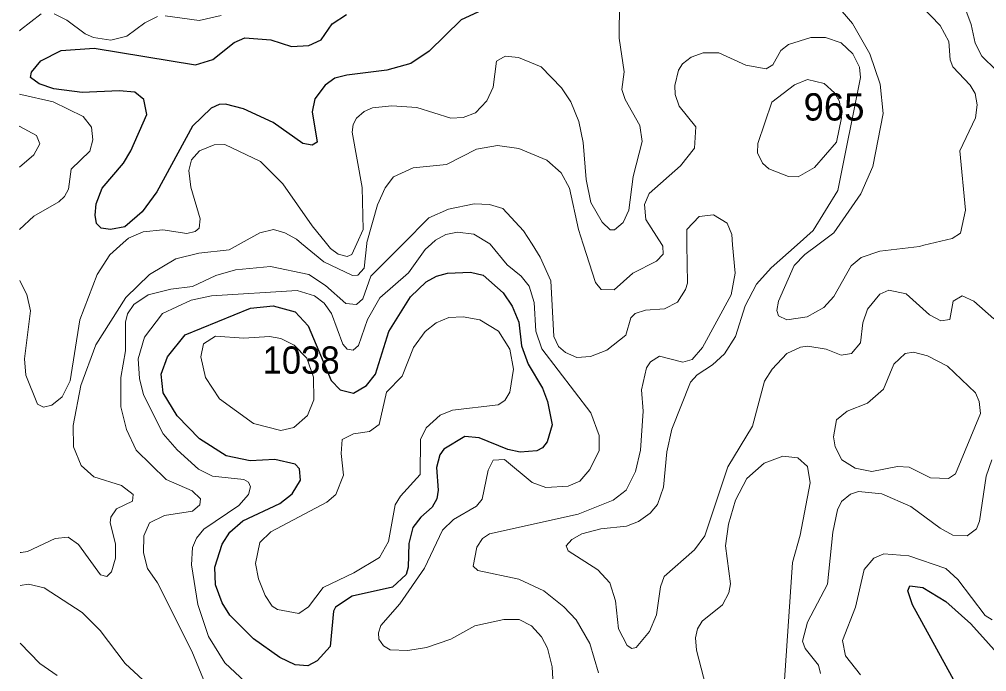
# Model space of a CAD drawing. Extents: x 473.9 to 500, y 7733.1 to 7760.8.
# Drawn here: x 473.9 to 476.736, y 7751.432 to 7753.344 of the extents above; entities that cross this region are included whole.
import ezdxf

# ---------------------------------------------------------------- set-up
doc = ezdxf.new("R2010")
doc.units = 0
doc.header["$LTSCALE"] = 0.032
doc.layers.add('1', color=7, linetype='Continuous', lineweight=25)
doc.layers.add('2', color=7, linetype='Continuous', lineweight=13)
doc.layers.add('21', color=7, linetype='Continuous')

msp = doc.modelspace()

# ---------------------------------------------------------------- linework, layer by layer
at = {"layer": '1'}
for points in [[(475.2698, 7753.3763), (475.1956, 7753.342), (475.1018, 7753.2501), (475.0478, 7753.2148), (474.9783, 7753.1952), (474.861, 7753.1806), (474.8255, 7753.171), (474.7973, 7753.1507), (474.767, 7753.1104), (474.7592, 7753.0728), (474.7738, 7752.9835), (474.7594, 7752.9748), (474.7316, 7752.98), (474.6449, 7753.0418), (474.5579, 7753.0818), (474.5049, 7753.095), (474.486, 7753.0939), (474.4628, 7753.0837), (474.4081, 7753.0306), (474.3035, 7752.8378), (474.2601, 7752.7799), (474.2093, 7752.7353), (474.1675, 7752.7282), (474.1406, 7752.7314), (474.1266, 7752.7453), (474.1224, 7752.7701), (474.1259, 7752.8035), (474.1436, 7752.8493), (474.2055, 7752.9226), (474.2271, 7752.958), (474.2746, 7753.0647), (474.2655, 7753.1084), (474.239, 7753.1302), (474.1933, 7753.1341), (474.085, 7753.1296), (474.0013, 7753.1404), (473.9587, 7753.1549)], [(473.9587, 7753.1549), (473.9328, 7753.1734), (473.9356, 7753.1888), (473.9632, 7753.2219), (474.0228, 7753.2522), (474.1199, 7753.2597), (474.4173, 7753.2102), (474.4673, 7753.226), (474.5301, 7753.2762), (474.5616, 7753.2892), (474.6377, 7753.2838), (474.6979, 7753.2638), (474.7494, 7753.2667), (474.7857, 7753.2839), (474.8175, 7753.331), (474.8592, 7753.3576)], [(476.7469, 7750.9887), (476.7341, 7750.9926), (476.7059, 7751.0101), (476.6612, 7751.0691), (476.624, 7751.1035), (476.6406, 7751.136), (476.6813, 7751.1644), (476.7054, 7751.1938), (476.7121, 7751.2206), (476.7103, 7751.2505), (476.6456, 7751.3979), (476.5186, 7751.6279), (476.5057, 7751.6682), (476.5109, 7751.6832), (476.5489, 7751.678), (476.6169, 7751.6368), (476.6899, 7751.5718), (476.7937, 7751.456)]]:
    msp.add_lwpolyline(points, dxfattribs=at)
msp.add_lwpolyline([(474.6496, 7752.0537), (474.5769, 7752.0498), (474.507, 7752.0644), (474.4285, 7752.1144), (474.3627, 7752.1811), (474.3221, 7752.2486), (474.3163, 7752.3035), (474.3345, 7752.3549), (474.3863, 7752.4186), (474.5782, 7752.4975), (474.6445, 7752.504), (474.7095, 7752.4862), (474.747, 7752.4452), (474.8147, 7752.2849), (474.8415, 7752.2575), (474.8805, 7752.2484), (474.9181, 7752.2705), (474.9444, 7752.3032), (474.9839, 7752.4289), (475.0476, 7752.5308), (475.0934, 7752.5742), (475.1234, 7752.5907), (475.1562, 7752.5998), (475.223, 7752.6028), (475.2603, 7752.594), (475.3187, 7752.5417), (475.3452, 7752.5031), (475.3648, 7752.4561), (475.3724, 7752.387), (475.3925, 7752.3333), (475.4344, 7752.2627), (475.4491, 7752.2239), (475.4625, 7752.1552), (475.4484, 7752.105), (475.4344, 7752.0876), (475.4173, 7752.0792), (475.3683, 7752.0753), (475.3328, 7752.0831), (475.2488, 7752.1172), (475.2064, 7752.1212), (475.1451, 7752.0842), (475.1334, 7752.0676), (475.1233, 7752.0298), (475.1288, 7751.9635), (475.1244, 7751.9379), (475.1108, 7751.9136), (475.0771, 7751.8842), (475.0541, 7751.8542), (475.0423, 7751.8074), (475.0406, 7751.7375), (475.0346, 7751.7167), (474.9946, 7751.6789), (474.8758, 7751.6533), (474.8275, 7751.6211), (474.8211, 7751.6086), (474.8116, 7751.5055), (474.7733, 7751.4636), (474.7465, 7751.4487), (474.7089, 7751.4512), (474.664, 7751.4729), (474.5874, 7751.528), (474.5176, 7751.5973), (474.4953, 7751.6337), (474.476, 7751.686), (474.4738, 7751.7377), (474.495, 7751.8058), (474.5177, 7751.8401), (474.556, 7751.8734), (474.6645, 7751.9242), (474.7004, 7751.9533), (474.7245, 7751.9925), (474.7216, 7752.0258), (474.7093, 7752.0401)], close=True, dxfattribs=at)
at = {"layer": '2'}
for points in [[(476.126, 7752.5176), (476.1211, 7752.4908), (476.126, 7752.475), (476.1511, 7752.4631), (476.2098, 7752.4715), (476.2594, 7752.4992), (476.2888, 7752.5316), (476.3394, 7752.621), (476.3681, 7752.6454), (476.4229, 7752.6642), (476.5395, 7752.6784), (476.5525, 7752.6815), (476.6349, 7752.701), (476.6598, 7752.7166), (476.6742, 7752.7847), (476.6575, 7752.9585), (476.7041, 7753.0551), (476.709, 7753.093), (476.7028, 7753.1264), (476.6883, 7753.1508), (476.6372, 7753.2047), (476.6299, 7753.225), (476.6258, 7753.2786), (476.6003, 7753.3257), (476.4617, 7753.4707)], [(473.9015, 7752.5778), (473.902, 7752.5769), (473.9226, 7752.5368), (473.9334, 7752.4893), (473.9153, 7752.3491), (473.9192, 7752.3011), (473.9534, 7752.2159), (473.971, 7752.2074), (473.9956, 7752.2128), (474.0263, 7752.2375), (474.0498, 7752.2839), (474.0782, 7752.4629), (474.1283, 7752.5954), (474.1657, 7752.6537), (474.2048, 7752.6887), (474.2205, 7752.7027), (474.263, 7752.721), (474.3215, 7752.7266), (474.3912, 7752.7163), (474.4157, 7752.722), (474.4273, 7752.7314), (474.431, 7752.7594), (474.4028, 7752.8523), (474.3973, 7752.9005), (474.4051, 7752.932), (474.4283, 7752.9586), (474.4714, 7752.9762), (474.5032, 7752.9766), (474.6073, 7752.9271), (474.6731, 7752.8617), (474.7588, 7752.7384), (474.8009, 7752.6869), (474.8127, 7752.6725), (474.8353, 7752.6557), (474.8617, 7752.6489), (474.875, 7752.6549), (474.8896, 7752.6866), (474.9085, 7752.7278), (474.9053, 7752.8505), (474.8766, 7753.0135), (474.8793, 7753.0359), (474.8892, 7753.0543), (474.9113, 7753.0738), (474.9363, 7753.0842), (474.9926, 7753.0908), (475.066, 7753.085), (475.1652, 7753.054), (475.202, 7753.056), (475.2381, 7753.0695), (475.2715, 7753.1054), (475.2897, 7753.1447), (475.2994, 7753.2217), (475.3249, 7753.2364), (475.3636, 7753.2324), (475.4305, 7753.2049), (475.4904, 7753.1428), (475.517, 7753.1018), (475.5404, 7753.044), (475.5538, 7752.983), (475.5622, 7752.8742), (475.5758, 7752.8065), (475.6091, 7752.7493), (475.6328, 7752.7269), (475.6449, 7752.7272), (475.6707, 7752.7485), (475.6878, 7752.7846), (475.6998, 7752.8832), (475.7264, 7752.9855), (475.7201, 7753.0322), (475.6764, 7753.1084), (475.667, 7753.1384), (475.6734, 7753.1903), (475.6589, 7753.2885), (475.66, 7753.3951)], [(476.2956, 7753.3875), (476.3427, 7753.3318), (476.394, 7753.2423), (476.424, 7753.1539), (476.433, 7753.0676), (476.4026, 7752.9122), (476.3678, 7752.8328), (476.2887, 7752.7182), (476.2411, 7752.6824), (476.2037, 7752.6544), (476.1719, 7752.6221), (476.126, 7752.5176)], [(476.6668, 7753.3945), (476.6914, 7753.3292), (476.7031, 7753.2739), (476.7222, 7753.2363), (476.8069, 7753.1538)], [(473.9644, 7753.36), (473.9037, 7753.3129), (473.9004, 7753.3103)], [(474.305, 7753.3521), (474.268, 7753.3337), (474.2153, 7753.2945), (474.1687, 7753.2824), (474.1177, 7753.2905), (474.0932, 7753.3013), (474.0396, 7753.3418), (474.0026, 7753.3602)], [(474.4925, 7753.3553), (474.4275, 7753.3402), (474.328, 7753.3545)], [(476.3001, 7752.8419), (476.3665, 7753.1731), (476.3634, 7753.2033), (476.3442, 7753.2431), (476.3101, 7753.2749), (476.2641, 7753.2904), (476.221, 7753.2904), (476.1558, 7753.2701), (476.1328, 7753.2526), (476.1092, 7753.2108), (476.09, 7753.1992), (476.0308, 7753.2098), (475.9517, 7753.2453), (475.9053, 7753.2461), (475.8704, 7753.2329), (475.8444, 7753.213), (475.8334, 7753.1946), (475.8221, 7753.1501), (475.823, 7753.1233), (475.8346, 7753.0893), (475.8839, 7753.0283), (475.88, 7752.966), (475.8389, 7752.9148), (475.7474, 7752.8335), (475.7334, 7752.8008), (475.7369, 7752.7573), (475.7841, 7752.6838), (475.787, 7752.6794), (475.7881, 7752.6555), (475.7683, 7752.6352), (475.6987, 7752.6001), (475.6439, 7752.5513), (475.606, 7752.5515), (475.5896, 7752.5725), (475.5537, 7752.6846), (475.5398, 7752.728), (475.5139, 7752.8494), (475.4889, 7752.8943), (475.4466, 7752.9311), (475.3644, 7752.9651), (475.3027, 7752.9744), (475.2408, 7752.9637), (475.1528, 7752.9182), (475.0553, 7752.909), (474.9976, 7752.8823), (474.973, 7752.8503), (474.9505, 7752.7997), (474.9195, 7752.6895), (474.9192, 7752.6865), (474.9111, 7752.6142), (474.8929, 7752.5939), (474.8776, 7752.593), (474.7934, 7752.6329), (474.7279, 7752.6871), (474.7131, 7752.6993), (474.6791, 7752.718), (474.6451, 7752.7275), (474.6052, 7752.7176), (474.551, 7752.6876), (474.5155, 7752.668), (474.4268, 7752.6583), (474.3591, 7752.642), (474.282, 7752.5961), (474.2129, 7752.5288), (474.1242, 7752.3896), (474.0807, 7752.2705), (474.0586, 7752.1528), (474.0589, 7752.0904), (474.0812, 7752.0355), (474.1184, 7752.0023), (474.1997, 7751.9777), (474.2341, 7751.9509), (474.2322, 7751.9317), (474.185, 7751.9087), (474.1686, 7751.8842), (474.1667, 7751.8681), (474.1827, 7751.8062), (474.1819, 7751.7639), (474.1702, 7751.7239), (474.1571, 7751.7108), (474.1386, 7751.7151), (474.0737, 7751.8048), (474.0439, 7751.8262), (474.0058, 7751.8221), (473.9247, 7751.784), (473.9054, 7751.7812), (473.9027, 7751.7808)], [(473.9007, 7753.1244), (473.9046, 7753.1235), (473.9993, 7753.1021), (474.0878, 7753.0587), (474.1119, 7753.0273), (474.116, 7752.9903), (474.1072, 7752.9575), (474.0519, 7752.9051), (474.0442, 7752.8462), (474.0331, 7752.8248), (474.0158, 7752.8089), (473.9426, 7752.7673), (473.9013, 7752.7281)], [(473.901, 7752.9108), (473.9429, 7752.9469), (473.96, 7752.9791), (473.9508, 7753.0034), (473.9021, 7753.0299), (473.9008, 7753.0306)], [(476.7572, 7752.466), (476.6985, 7752.5173), (476.6647, 7752.5338), (476.6383, 7752.5175), (476.6284, 7752.4641), (476.6017, 7752.4596), (476.5687, 7752.4778), (476.5001, 7752.5395), (476.4495, 7752.5504), (476.4233, 7752.5381), (476.3867, 7752.494), (476.3731, 7752.4543), (476.3663, 7752.3955), (476.3407, 7752.3642), (476.3102, 7752.3589), (476.2658, 7752.3769), (476.2126, 7752.3858), (476.1906, 7752.3831), (476.1506, 7752.3644), (476.1074, 7752.3184), (476.0853, 7752.2833), (476.0497, 7752.151), (475.9773, 7752.032), (475.91, 7751.8299), (475.8797, 7751.7889), (475.7908, 7751.7101), (475.7798, 7751.6803), (475.7682, 7751.5979), (475.7476, 7751.5492), (475.7088, 7751.5028), (475.6961, 7751.499), (475.6827, 7751.5083), (475.6573, 7751.557), (475.6484, 7751.6391), (475.6312, 7751.6916), (475.5961, 7751.7297), (475.5096, 7751.7853), (475.5038, 7751.8006), (475.5199, 7751.8191), (475.5496, 7751.8358), (475.6053, 7751.8505), (475.6808, 7751.8581), (475.7157, 7751.8716), (475.7497, 7751.8962), (475.771, 7751.922), (475.789, 7751.9725), (475.7986, 7752.076), (475.8135, 7752.1424), (475.8682, 7752.2802), (475.8878, 7752.3022), (475.9323, 7752.3309), (475.9683, 7752.3634), (476.0003, 7752.4142), (476.0282, 7752.5042), (476.0614, 7752.5676), (476.1046, 7752.6153), (476.1805, 7752.6826), (476.2282, 7752.725), (476.3001, 7752.8419)], [(474.4405, 7751.4086), (474.4057, 7751.4912), (474.3053, 7751.6916), (474.2757, 7751.7338), (474.2647, 7751.7796), (474.2652, 7751.83), (474.2819, 7751.8681), (474.3259, 7751.8896), (474.4076, 7751.9019), (474.4294, 7751.9211), (474.4313, 7751.9386), (474.407, 7751.9621), (474.3312, 7751.9948), (474.2433, 7752.0806), (474.2147, 7752.1419), (474.1981, 7752.2078), (474.198, 7752.2941), (474.2116, 7752.3719), (474.2113, 7752.4564), (474.2171, 7752.4805), (474.2358, 7752.5081), (474.2783, 7752.5358), (474.345, 7752.5529), (474.4076, 7752.561), (474.4764, 7752.5928), (474.5338, 7752.6094), (474.6367, 7752.6198), (474.7488, 7752.5955), (474.7976, 7752.5633), (474.8575, 7752.5113), (474.8888, 7752.5077), (474.9074, 7752.5243), (474.9305, 7752.5909), (475.0253, 7752.6862), (475.1008, 7752.762), (475.1587, 7752.7877), (475.2342, 7752.8029), (475.2788, 7752.8007), (475.3175, 7752.7895), (475.3787, 7752.724), (475.4035, 7752.685), (475.4279, 7752.6467), (475.4584, 7752.5777), (475.4676, 7752.4143), (475.4813, 7752.3852), (475.5018, 7752.3675), (475.5345, 7752.3524), (475.5747, 7752.3554), (475.6233, 7752.3739), (475.6782, 7752.4177), (475.693, 7752.4684), (475.7058, 7752.4819), (475.7361, 7752.4911), (475.7923, 7752.4952), (475.8296, 7752.515), (475.8534, 7752.5515), (475.859, 7752.5708), (475.8578, 7752.6836), (475.8573, 7752.7282), (475.8932, 7752.7657), (475.9354, 7752.7704), (475.9756, 7752.7467), (475.9892, 7752.7128), (475.9918, 7752.6832), (475.999, 7752.5994), (475.9875, 7752.5363), (475.9029, 7752.3821), (475.8732, 7752.3468), (475.846, 7752.3392), (475.7775, 7752.356), (475.7511, 7752.3395), (475.739, 7752.3224), (475.7241, 7752.2577), (475.7297, 7752.1949), (475.7216, 7752.0806), (475.7066, 7752.0186), (475.6799, 7751.9637), (475.6417, 7751.9343), (475.5387, 7751.8933), (475.2788, 7751.8355), (475.2583, 7751.8219), (475.2414, 7751.7968), (475.2311, 7751.7411), (475.2446, 7751.7285), (475.3645, 7751.7031), (475.4385, 7751.6685), (475.4964, 7751.6219), (475.5334, 7751.5833)], [(474.953, 7751.5458), (474.9607, 7751.5665), (475.016, 7751.6305), (475.0881, 7751.7352), (475.1413, 7751.8459), (475.1737, 7751.8781), (475.2407, 7751.9164), (475.2577, 7751.9377), (475.2746, 7752.0223), (475.2894, 7752.0515), (475.323, 7752.0532), (475.4041, 7751.9864), (475.4439, 7751.9716), (475.5093, 7751.9758), (475.5439, 7751.9903), (475.5731, 7752.0244), (475.6, 7752.0797), (475.6008, 7752.1242), (475.5755, 7752.1905), (475.4324, 7752.3777), (475.4147, 7752.4298), (475.4095, 7752.5133), (475.3952, 7752.562), (475.3718, 7752.5908), (475.3304, 7752.6241), (475.2806, 7752.6852), (475.2803, 7752.6854), (475.2327, 7752.714), (475.1855, 7752.7195), (475.1512, 7752.7132), (475.1207, 7752.6963), (475.109, 7752.6859), (475.0905, 7752.6695), (475.0414, 7752.6005), (474.9572, 7752.5276), (474.9212, 7752.4639), (474.8946, 7752.3874), (474.8787, 7752.374), (474.8611, 7752.3768), (474.8492, 7752.3912), (474.8159, 7752.4811), (474.7938, 7752.512), (474.7653, 7752.5335), (474.7146, 7752.549), (474.464, 7752.5337), (474.4038, 7752.5206), (474.3201, 7752.482), (474.2676, 7752.4117), (474.2492, 7752.349), (474.2524, 7752.2908), (474.2643, 7752.2433), (474.3219, 7752.1288), (474.3627, 7752.0818), (474.4256, 7752.0249), (474.4666, 7752.0048), (474.5583, 7751.9947), (474.572, 7751.9871), (474.5786, 7751.973), (474.5724, 7751.9509), (474.5436, 7751.9187), (474.4415, 7751.8495), (474.4201, 7751.8228), (474.4084, 7751.7958), (474.4054, 7751.7452), (474.4236, 7751.6282), (474.4552, 7751.5343), (474.5025, 7751.4574), (474.5624, 7751.4022)], [(475.9127, 7751.3887), (475.8856, 7751.4949), (475.8829, 7751.5307), (475.8887, 7751.5571), (475.9021, 7751.5799), (475.9616, 7751.6272), (475.9804, 7751.6622), (475.9851, 7751.6888), (475.9709, 7751.8004), (475.9795, 7751.8642), (476.0004, 7751.934), (476.0337, 7751.9979), (476.084, 7752.0426), (476.1386, 7752.0632), (476.1825, 7752.0588), (476.2114, 7752.0331), (476.2192, 7751.9848), (476.1901, 7751.8321), (476.1676, 7751.7512), (476.144, 7751.407)], [(476.249, 7751.4257), (476.2439, 7751.4505), (476.2039, 7751.4991), (476.1968, 7751.5207), (476.2111, 7751.5764), (476.2696, 7751.6885), (476.2856, 7751.8405), (476.2988, 7751.906), (476.3114, 7751.9303), (476.3369, 7751.952), (476.3604, 7751.9596), (476.4292, 7751.9524), (476.5143, 7751.9154), (476.6002, 7751.8518), (476.637, 7751.8315), (476.6796, 7751.8294), (476.7068, 7751.8501), (476.7153, 7751.8728), (476.7349, 7752.0051), (476.7513, 7752.0524)], [(476.7525, 7751.5834), (476.7319, 7751.5963), (476.6522, 7751.7019), (476.6172, 7751.7336), (476.5084, 7751.7713), (476.4352, 7751.7771), (476.4055, 7751.7638), (476.3773, 7751.7308), (476.3519, 7751.6203), (476.3134, 7751.5233), (476.323, 7751.4777), (476.3664, 7751.4225)], [(473.9029, 7751.6846), (473.9276, 7751.6878), (473.9736, 7751.6774), (474.0846, 7751.605), (474.1376, 7751.552), (474.2109, 7751.4555), (474.2884, 7751.3835)], [(475.4643, 7751.4091), (475.4627, 7751.4461), (475.4486, 7751.5004), (475.431, 7751.534), (475.4023, 7751.5655), (475.366, 7751.5846), (475.3205, 7751.5843), (475.236, 7751.5664), (475.1658, 7751.5267), (475.0939, 7751.5028), (475.0397, 7751.4934), (474.9881, 7751.4951), (474.9678, 7751.5073), (474.9541, 7751.5265), (474.953, 7751.5458)], [(475.5334, 7751.5833), (475.5728, 7751.5142), (475.5984, 7751.428)], [(474.0117, 7751.4204), (473.9604, 7751.4559), (473.9031, 7751.5152)]]:
    msp.add_lwpolyline(points, dxfattribs=at)
for points in [[(476.2967, 7752.9835), (476.3108, 7753.0551), (476.305, 7753.1033), (476.2908, 7753.1286), (476.2601, 7753.1558), (476.211, 7753.1673), (476.1727, 7753.1519), (476.107, 7753.1015), (476.066, 7752.9802), (476.0649, 7752.9526), (476.0792, 7752.922), (476.0977, 7752.9056), (476.1557, 7752.8835), (476.1835, 7752.8825), (476.2322, 7752.9092)], [(475.0758, 7752.0096), (475.0769, 7752.1124), (475.0929, 7752.1461), (475.1338, 7752.1836), (475.1705, 7752.1986), (475.3044, 7752.2137), (475.3235, 7752.2266), (475.3388, 7752.2507), (475.3494, 7752.3184), (475.3382, 7752.3773), (475.3054, 7752.4294), (475.2509, 7752.4629), (475.2021, 7752.4718), (475.1592, 7752.4694), (475.1228, 7752.4545), (475.0907, 7752.4287), (475.0562, 7752.3822), (475.0226, 7752.2977), (474.977, 7752.2505), (474.9554, 7752.1562), (474.9267, 7752.1355), (474.88, 7752.129), (474.8466, 7752.1123), (474.8436, 7752.0712), (474.8508, 7752.0079), (474.8284, 7751.9508), (474.8022, 7751.928), (474.6382, 7751.8417), (474.6057, 7751.8099), (474.5929, 7751.7483), (474.6018, 7751.7034), (474.6214, 7751.6547), (474.6421, 7751.6235), (474.6576, 7751.6137), (474.7195, 7751.6021), (474.7483, 7751.6215), (474.7908, 7751.6786), (474.8812, 7751.7211), (474.9561, 7751.766), (474.9826, 7751.8133), (475.0025, 7751.9205), (475.018, 7751.946)], [(474.7457, 7752.1821), (474.7641, 7752.2281), (474.7631, 7752.2952), (474.7433, 7752.3505), (474.7063, 7752.3883), (474.6673, 7752.4078), (474.6334, 7752.414), (474.5584, 7752.409), (474.4755, 7752.4149), (474.4401, 7752.3923), (474.4328, 7752.3542), (474.4461, 7752.2935), (474.4873, 7752.2315), (474.5866, 7752.1593), (474.6673, 7752.139), (474.7048, 7752.1475)], [(476.7185, 7752.1885), (476.7145, 7752.2233), (476.7038, 7752.2493), (476.6218, 7752.3269), (476.5626, 7752.3576), (476.5223, 7752.368), (476.4977, 7752.3638), (476.4644, 7752.3331), (476.4339, 7752.2602), (476.3868, 7752.2191), (476.3278, 7752.1952), (476.2961, 7752.1696), (476.2876, 7752.1201), (476.2919, 7752.091), (476.3116, 7752.0528), (476.3508, 7752.028), (476.4001, 7752.0183), (476.4752, 7752.0327), (476.5095, 7752.0312), (476.5717, 7751.9993), (476.6247, 7751.998), (476.6447, 7752.0116)]]:
    msp.add_lwpolyline(points, close=True, dxfattribs=at)

# ---------------------------------------------------------------- texts
at = {"layer": '21'}
msp.add_text('965', height=0.08, dxfattribs=at).set_placement((476.1998, 7753.0472))
at = {"layer": '21', "width": 0.95}
msp.add_text('1038', height=0.08, dxfattribs=at).set_placement((474.6135, 7752.305))

doc.saveas('drawing.dxf')
